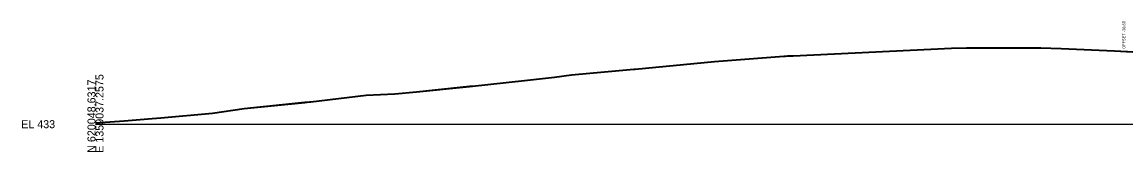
# Model space of a CAD drawing. Extents: x -26 to 803, y -27 to 3586.
# Drawn here: x -25.7 to 360.6, y 2490.3 to 2535.7 of the extents above; entities that cross this region are included whole.
import ezdxf

# ---------------------------------------------------------------- set-up
doc = ezdxf.new("R2010")
doc.units = 0
for name, color, linetype in [('DESIGN - SHEET - Light Grid', 7, 'Continuous'), ('DESIGN - TYPICAL - Slope Tie Text', 7, 'Continuous'), ('SURVEY - GROUND - Bottom of Topsoil Layer', 7, 'Continuous'), ('SURVEY - GROUND - Top of Ground', 7, 'Continuous')]:
    doc.layers.add(name, color=color, linetype=linetype)

msp = doc.modelspace()

# ---------------------------------------------------------------- linework, layer by layer
at = {"layer": 'DESIGN - SHEET - Light Grid'}
msp.add_line((0, 2500), (400, 2500), dxfattribs=at)
at = {"layer": 'SURVEY - GROUND - Bottom of Topsoil Layer'}
for p, q in [((244.13, 2523.83), (299.59, 2526.51)), ((299.59, 2526.51), (304.84, 2526.62)), ((304.84, 2526.62), (324.17, 2526.56)), ((324.17, 2526.56), (330.18, 2526.53)), ((330.18, 2526.53), (330.81, 2526.54)), ((330.81, 2526.54), (338, 2526.36)), ((216.67, 2521.79), (240.91, 2523.64)), ((240.91, 2523.64), (241.48, 2523.7)), ((241.48, 2523.7), (242.23, 2523.74)), ((242.23, 2523.74), (244.13, 2523.83)), ((338, 2526.36), (356.65, 2525.58)), ((356.65, 2525.58), (374.68, 2524.59)), ((166.56, 2517.09), (188.36, 2519.07)), ((188.36, 2519.07), (188.88, 2519.12)), ((188.88, 2519.12), (216.67, 2521.79)), ((131.93, 2513.22), (150.15, 2515.15)), ((150.15, 2515.15), (160.67, 2516.31)), ((160.67, 2516.31), (166.56, 2517.09)), ((104.78, 2510.48), (112.33, 2511.22)), ((112.33, 2511.22), (130.87, 2513.11)), ((130.87, 2513.11), (131.45, 2513.18)), ((131.45, 2513.18), (131.93, 2513.22)), ((52.07, 2505.33), (73.21, 2507.52)), ((73.21, 2507.52), (74.93, 2507.7)), ((74.93, 2507.7), (75.33, 2507.73)), ((75.33, 2507.73), (94.72, 2510)), ((94.72, 2510), (104.78, 2510.48)), ((22.91, 2502.12), (40.9, 2503.77)), ((40.9, 2503.77), (52.07, 2505.33)), ((0, 2500.37), (9.98, 2501.04)), ((9.98, 2501.04), (19.89, 2501.87)), ((19.89, 2501.87), (22.91, 2502.12))]:
    msp.add_line(p, q, dxfattribs=at)
at = {"layer": 'SURVEY - GROUND - Top of Ground'}
msp.add_lwpolyline([(0, 2500.62), (9.98, 2501.29), (19.89, 2502.12), (22.91, 2502.37), (40.9, 2504.02), (52.07, 2505.58), (73.21, 2507.77), (74.93, 2507.95), (75.33, 2507.98), (94.72, 2510.25), (104.78, 2510.73), (112.33, 2511.47), (130.87, 2513.36), (131.45, 2513.43), (131.93, 2513.47), (150.15, 2515.4), (160.67, 2516.56), (166.56, 2517.34), (188.36, 2519.32), (188.88, 2519.37), (216.67, 2522.04), (240.91, 2523.89), (241.48, 2523.95), (242.23, 2523.99), (244.13, 2524.08), (299.59, 2526.76), (304.84, 2526.87), (324.17, 2526.81), (330.18, 2526.78), (330.81, 2526.79), (338, 2526.61), (356.65, 2525.83), (374.68, 2524.84)], dxfattribs=at)

# ---------------------------------------------------------------- texts
at = {"layer": 'DESIGN - SHEET - Light Grid'}
for s, p in [('N 620048.6317', (0, 2490)), ('E 1359037.2575', (2.8, 2490))]:
    msp.add_text(s, height=2.8, rotation=90, dxfattribs=at).set_placement(p)
msp.add_text('EL 433', height=2.8, dxfattribs=at).set_placement((-26, 2498.6))
at = {"layer": 'DESIGN - TYPICAL - Slope Tie Text'}
msp.add_text('OFFSET -38.60', height=1, rotation=90, dxfattribs=at).set_placement((360.4, 2526.32))

doc.saveas('drawing.dxf')
